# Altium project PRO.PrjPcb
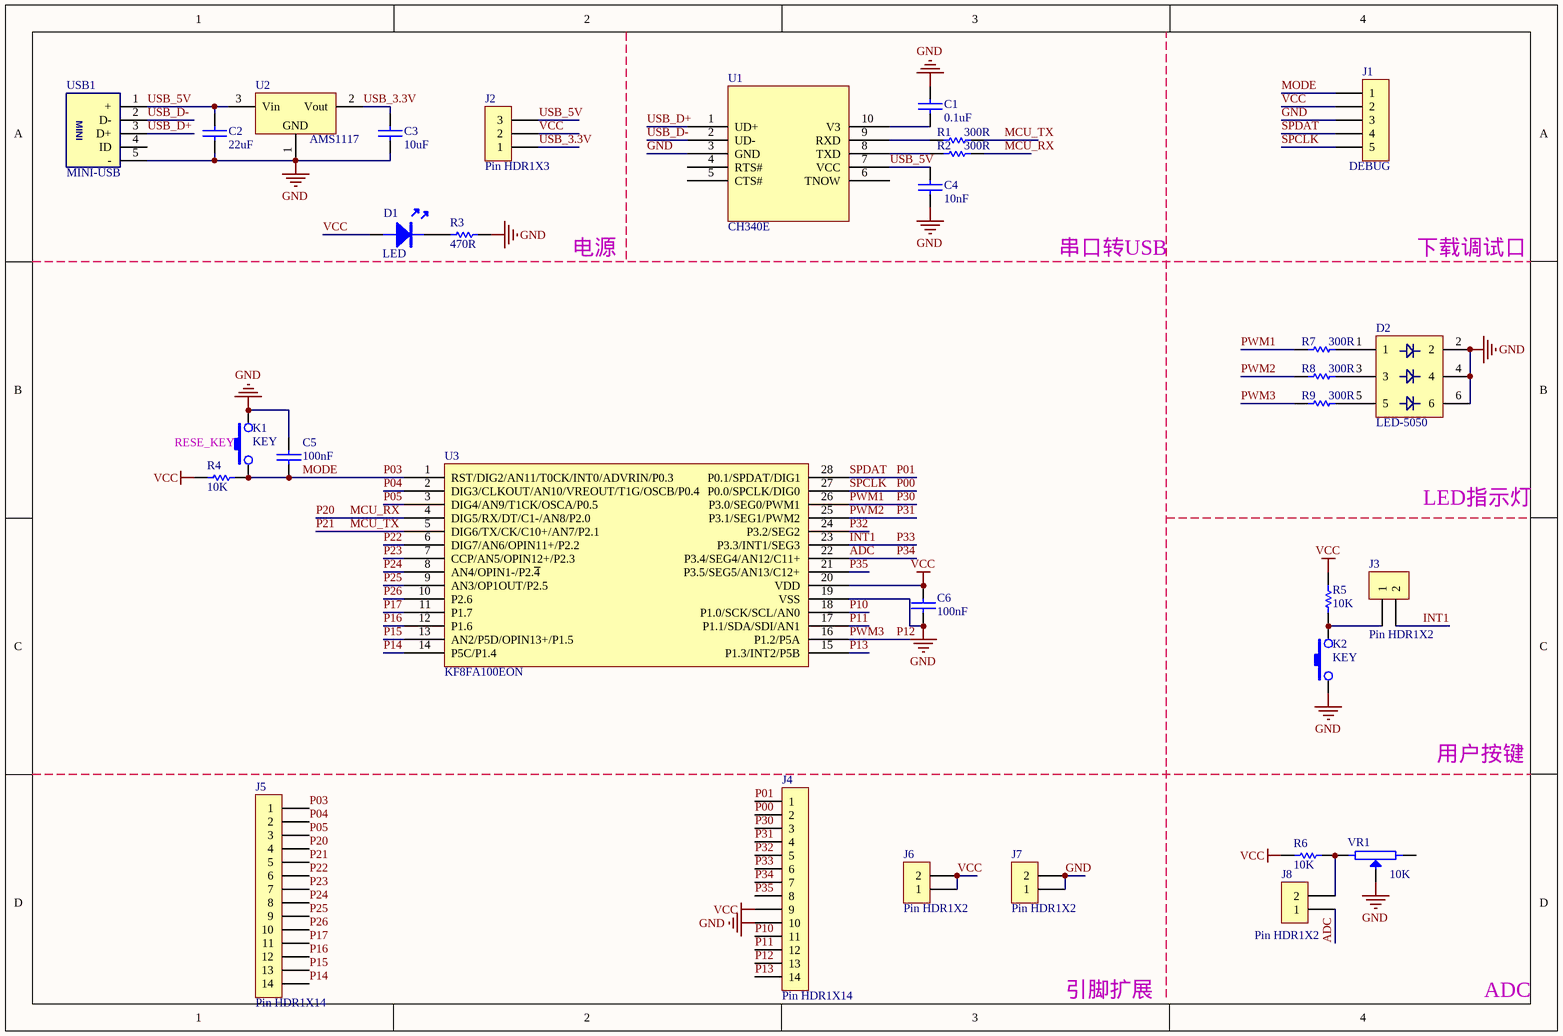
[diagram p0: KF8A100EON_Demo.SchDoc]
1 sheet, 32 parts. Net scope: global (net labels, ports and power ports of the same name join across sheets).
Board file: KF8A100EON_Demo.PcbDoc

## Sheet KF8A100EON_Demo.SchDoc
size A4

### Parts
C1  0.1uF  [0603C]
C2  22uF  [0603C]
C3  10uF  [0603C]
C4  10nF  [0603C]
C5  100nF  [0603C]
C6  100nF  [0603C]
D1  LED  [LED-0603B]
D2  LED-5050  [LED-5050W]
J1  DEBUG  [Pin HDR1X5/2.54mm-S]
J2  Pin HDR1X3  [Pin HDR1X3/2.54mm-S]
J3  Pin HDR1X2  [Pin HDR1X2/2.54mm-S]
J4  Pin HDR1X14  [Pin HDR1X14/2.54mm-S]
J5  Pin HDR1X14  [Pin HDR1X14/2.54mm-S]
J6  Pin HDR1X2  [Pin HDR1X2/2.54mm-S]
J7  Pin HDR1X2  [Pin HDR1X2/2.54mm-S]
J8  Pin HDR1X2  [Pin HDR1X2/2.54mm-S]
K1  KEY  [DIP-6X6X4.3]
K2  KEY  [DIP-6X6X4.3]
R1  300R  [0603R]
R2  300R  [0603R]
R3  470R  [0603R]
R4  10K  [0603R]
R5  10K  [0603R]
R6  10K  [0603R]
R7  300R  [0603R]
R8  300R  [0603R]
R9  300R  [0603R]
U1  CH340E  [MSOP10]
U2  AMS1117  [SOT223]
U3  KF8FA100EON  [SSOP28]
USB1  MINI-USB  [USB-MINI-A]
VR1  10K  [3296W]

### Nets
GND: C1.2 C2.1 C3.1 C4.1 C5.2 C6.1 D2.2 D2.4 D2.6 J1.3 J4.10 J7.1 J7.2 K1.3 K2.1 R3.1 U1.3(GND) U2.1(GND) U3.19(VSS) USB1.5(-) VR1.2
VCC: C6.2 D1.A J1.2 J2.2 J4.9 J6.1 J6.2 R4.2 R5.1 R6.1 U3.20(VDD)
ADC: J4.7 J8.1 U3.22(P3.4/SEG4/AN12/C11+)  [also labelled P34]
INT1: J3.2 J4.6 U3.23(P3.3/INT1/SEG3)  [also labelled P33]
MCU_RX: J5.4 R2.1 U3.4(DIG5/RX/DT/C1-/AN8/P2.0)  [also labelled P20]
MCU_TX: J5.5 R1.1 U3.5(DIG6/TX/CK/C10+/AN7/P2.1)  [also labelled P21]
MODE: C5.1 J1.1 J5.1 K1.1 R4.1 U3.1(RST/DIG2/AN11/T0CK/INT0/ADVRIN/P0.3)  [also labelled P03]
P00: J1.5 J4.2 U3.27(P0.0/SPCLK/DIG0)  [also labelled SPCLK]
P01: J1.4 J4.1 U3.28(P0.1/SPDAT/DIG1)  [also labelled SPDAT]
P04: J5.2 U3.2(DIG3/CLKOUT/AN10/VREOUT/T1G/OSCB/P0.4)
P05: J5.3 U3.3(DIG4/AN9/T1CK/OSCA/P0.5)
P10: J4.11 U3.18(P1.0/SCK/SCL/AN0)
P11: J4.12 U3.17(P1.1/SDA/SDI/AN1)
P12: J4.13 R9.2 U3.16(P1.2/P5A)  [also labelled PWM3]
P13: J4.14 U3.15(P1.3/INT2/P5B)
P14: J5.14 U3.14(P5C/P1.4)
P15: J5.13 U3.13(AN2/P5D/OPIN13+/P1.5)
P16: J5.12 U3.12(P1.6)
P17: J5.11 U3.11(P1.7)
P22: J5.6 U3.6(DIG7/AN6/OPIN11+/P2.2)
P23: J5.7 U3.7(CCP/AN5/OPIN12+/P2.3)
P24: J5.8 U3.8(AN4/OPIN1-/P2.~{4})
P25: J5.9 U3.9(AN3/OP1OUT/P2.5)
P26: J5.10 U3.10(P2.6)
P30: J4.3 R7.2 U3.26(P3.0/SEG0/PWM1)  [also labelled PWM1]
P31: J4.4 R8.2 U3.25(P3.1/SEG1/PWM2)  [also labelled PWM2]
P32: J4.5 U3.24(P3.2/SEG2)
P35: J4.8 U3.21(P3.5/SEG5/AN13/C12+)
USB_3.3V: C3.2 J2.1 U2.2(Vout)
USB_5V: C2.2 C4.2 J2.3 U1.7(VCC) U2.3(Vin) USB1.1(+)
USB_D+: U1.1(UD+) USB1.3(D+)
USB_D-: U1.2(UD-) USB1.2(D-)
NetC1_1: C1.1 U1.10(V3)
NetD1_K: D1.K R3.2
NetD2_1: D2.1 R7.1
NetD2_3: D2.3 R8.1
NetD2_5: D2.5 R9.1
NetJ3_1: J3.1 K2.3 R5.2
NetJ8_2: J8.2 R6.2 VR1.3
NetR1_2: R1.2 U1.9(RXD)
NetR2_2: R2.2 U1.8(TXD)

Not connected (* = marked no-connect by the designer): U1 4(RTS#) 5(CTS#) 6(TNOW); USB1 4(ID); VR1 1

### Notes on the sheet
- 电源
- 串口转USB
- 下载调试口
- RESE_KEY
- LED指示灯
- 用户按键
- 引脚扩展
- ADC

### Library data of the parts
C1-C6 = CAP: 无极性电容
J1 = Pin HDR1X5
R1-R9 = RES
U1 = CH340E: USB to TTL Serial / UART
U2 = AMS1117: 三端稳压芯片
U3 = KF8FA100EON: SSOP28/TSSOP28
VR1 = RESVR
